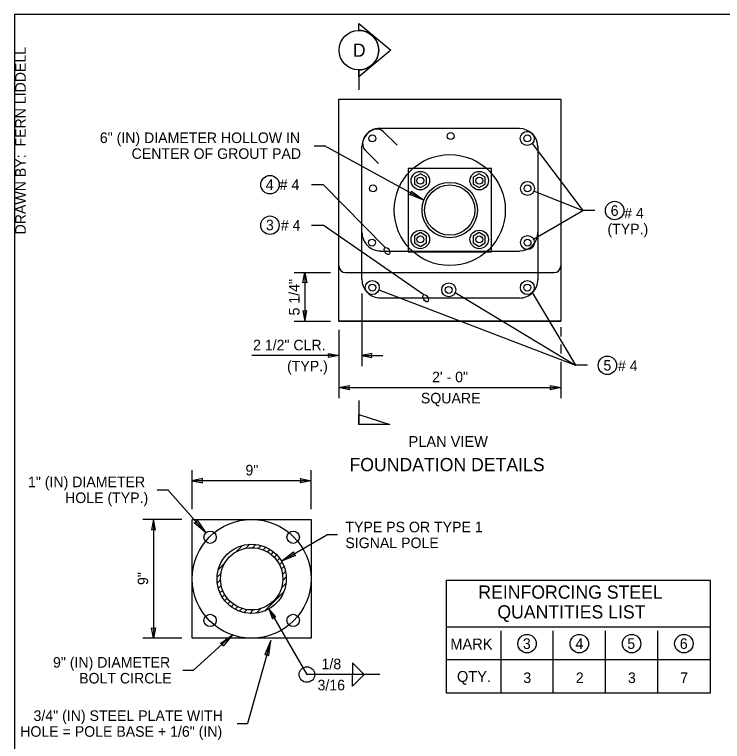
# Model space of a CAD drawing. Extents: x 99862 to 103680, y 99470 to 105076.
# Drawn here: x 99862 to 100935, y 103974 to 105076 of the extents above; entities that cross this region are included whole.
import ezdxf

# ---------------------------------------------------------------- set-up
doc = ezdxf.new("R2010")
doc.units = 0
for name, color, linetype in [('Level 1', 7, 'Continuous'), ('Level 10', 7, 'Continuous'), ('Level 13', 7, 'Continuous'), ('Level 15', 7, 'Continuous'), ('Level 20', 7, 'Continuous'), ('Level 24', 7, 'Continuous'), ('Level 25', 7, 'Continuous'), ('Level 26', 7, 'Continuous'), ('Level 4', 7, 'Continuous'), ('Level 40', 7, 'Continuous'), ('Level 5', 7, 'Continuous'), ('Level 62', 7, 'Continuous'), ('Level 8', 7, 'Continuous'), ('Level 9', 7, 'Continuous')]:
    doc.layers.add(name, color=color, linetype=linetype)

msp = doc.modelspace()

# ---------------------------------------------------------------- linework, layer by layer
at = {"layer": 'Level 1'}
msp.add_line((100363.4, 104684.6), (100679.6, 104684.6), dxfattribs=at)
for points in [[(100353.4, 104947.3), (100689.6, 104947.3), (100689.6, 104774.6)], [(100353.4, 104694.6), (100353.4, 104947.3)], [(100689.6, 104774.6), (100689.6, 104694.6)], [(100689.6, 104694.6), (100689.6, 104611.1), (100353.4, 104611.1), (100353.4, 104694.6)]]:
    msp.add_lwpolyline(points, dxfattribs=at)
for centre, start, end in [((100363.4, 104694.6), 180, 270), ((100679.6, 104694.6), 270, 0)]:
    msp.add_arc(centre, 10, start, end, dxfattribs=at)
at = {"layer": 'Level 10'}
for centre in [(100404, 104887.8), (100523, 104891.3), (100638.9, 104887.8), (100405.2, 104812), (100639.3, 104812), (100403.8, 104730), (100639.3, 104730), (100404.1, 104661.8), (100519.9, 104658.3), (100639, 104661.8)]:
    msp.add_circle(centre, 5.25, dxfattribs=at)
at = {"layer": 'Level 13'}
for p, q in [((100476.9, 104834.3), (100467.8, 104829.1)), ((100467.8, 104829.1), (100467.8, 104818.6)), ((100486, 104829.1), (100476.9, 104834.3)), ((100486, 104818.6), (100486, 104829.1)), ((100566.1, 104834.3), (100557, 104829.1)), ((100557, 104829.1), (100557, 104818.6)), ((100575.2, 104829.1), (100566.1, 104834.3)), ((100575.2, 104818.6), (100575.2, 104829.1)), ((100467.8, 104818.6), (100476.9, 104813.3)), ((100476.9, 104813.3), (100486, 104818.6)), ((100557, 104818.6), (100566.1, 104813.3)), ((100566.1, 104813.3), (100575.2, 104818.6)), ((100476.9, 104745.2), (100467.8, 104739.9)), ((100467.8, 104739.9), (100467.8, 104729.4)), ((100486, 104739.9), (100476.9, 104745.2)), ((100486, 104729.4), (100486, 104739.9)), ((100566.1, 104745.2), (100557, 104739.9)), ((100557, 104739.9), (100557, 104729.4)), ((100575.2, 104739.9), (100566.1, 104745.2)), ((100575.2, 104729.4), (100575.2, 104739.9)), ((100467.8, 104729.4), (100476.9, 104724.1)), ((100476.9, 104724.1), (100486, 104729.4)), ((100557, 104729.4), (100566.1, 104724.1)), ((100566.1, 104724.1), (100575.2, 104729.4))]:
    msp.add_line(p, q, dxfattribs=at)
msp.add_lwpolyline([(100584.6, 104842.3), (100458.5, 104842.3), (100458.5, 104716.2), (100584.6, 104716.2)], close=True, dxfattribs=at)
for centre in [(100476.9, 104823.8), (100566.1, 104823.8), (100476.9, 104734.7), (100566.1, 104734.7)]:
    msp.add_circle(centre, 14, dxfattribs=at)
at = {"layer": 'Level 15'}
for p, q in [((100646.4, 104880.3), (100723.3, 104778.5)), ((100315.8, 104876.8), (100331.8, 104876.8)), ((100482, 104794.2), (100331.8, 104876.8)), ((100311.8, 104817.8), (100329.7, 104817.8)), ((100423.4, 104722.4), (100329.7, 104817.8)), ((100649.4, 104807.9), (100723.3, 104778.5)), ((100648.5, 104735.3), (100723.3, 104778.5)), ((100741.2, 104778.5), (100723.3, 104778.5)), ((100311.8, 104756.2), (100329.7, 104756.2)), ((100482, 104650.8), (100329.7, 104756.2)), ((100285.8, 104684.6), (100340.8, 104684.6)), ((100301.8, 104684.6), (100301.8, 104611.1)), ((100388, 104652.7), (100388, 104542.7)), ((100414.1, 104658.2), (100712.2, 104544.3)), ((100529.8, 104654.3), (100712.2, 104544.3)), ((100646.5, 104654.2), (100712.2, 104544.3)), ((100285.8, 104611.1), (100340.8, 104611.1)), ((100353.4, 104597.6), (100353.4, 104494.2)), ((100689.6, 104601.6), (100689.6, 104587.7)), ((100689.6, 104575.7), (100689.6, 104561.7)), ((100353.4, 104558.7), (100221.6, 104558.7)), ((100387.8, 104558.7), (100419.8, 104558.7)), ((100689.6, 104549.1), (100689.6, 104494.2)), ((100730.1, 104544.3), (100712.2, 104544.3)), ((100353.4, 104510.2), (100689.6, 104510.2)), ((100131.3, 104326.2), (100131.3, 104385.2)), ((100311.3, 104326.2), (100311.3, 104385.2)), ((100311.3, 104369.2), (100131.3, 104369.2)), ((100078.3, 104355.3), (100094.3, 104355.3)), ((100151.7, 104290.1), (100094.3, 104355.3)), ((100115.5, 104310.5), (100056.5, 104310.5)), ((100072.5, 104310.5), (100072.5, 104130.5)), ((100266.4, 104247.2), (100335.3, 104287)), ((100351.3, 104287), (100335.3, 104287)), ((100247.5, 104175.1), (100305, 104075.5)), ((100115.5, 104130.5), (100056.5, 104130.5)), ((100192.8, 104136.2), (100133.1, 104081.9)), ((100250.4, 104127), (100215.1, 104001.2)), ((100374.2, 104093), (100374.2, 104075.5)), ((100374.2, 104093), (100391.7, 104075.5)), ((100117.1, 104081.9), (100133.1, 104081.9)), ((100415.5, 104075.5), (100305, 104075.5)), ((100374.2, 104058), (100391.7, 104075.5)), ((100374.2, 104058), (100374.2, 104075.5)), ((100199.1, 104001.2), (100215.1, 104001.2))]:
    msp.add_line(p, q, dxfattribs=at)
for points in [[(100482, 104794.2), (100460.5, 104802.6), (100462.9, 104804.7), (100463.4, 104807.8)], [(100301.8, 104684.6), (100304.9, 104668.9), (100301.8, 104669.6), (100298.7, 104668.9)], [(100301.8, 104611.1), (100304.9, 104626.8), (100301.8, 104626.1), (100298.7, 104626.8)], [(100353.4, 104558.7), (100337.7, 104555.6), (100338.4, 104558.7), (100337.7, 104561.7)], [(100387.8, 104558.7), (100403.5, 104555.6), (100402.8, 104558.7), (100403.5, 104561.7)], [(100353.4, 104510.2), (100369.1, 104513.3), (100368.4, 104510.2), (100369.1, 104507.1)], [(100689.6, 104510.2), (100673.9, 104507.1), (100674.6, 104510.2), (100673.9, 104513.3)], [(100131.3, 104369.2), (100147, 104366.1), (100146.3, 104369.2), (100147, 104372.3)], [(100311.3, 104369.2), (100295.5, 104366.1), (100296.3, 104369.2), (100295.5, 104372.3)], [(100072.5, 104310.5), (100069.4, 104294.8), (100072.5, 104295.5), (100075.6, 104294.8)], [(100151.7, 104290.1), (100134.3, 104305.2), (100137.3, 104306.4), (100138.8, 104309.2)], [(100266.4, 104247.2), (100284.7, 104261.2), (100285.3, 104258.1), (100287.7, 104256)], [(100247.5, 104175.1), (100252.7, 104159.9), (100255, 104162.1), (100258, 104163)], [(100072.5, 104130.5), (100069.4, 104146.2), (100072.5, 104145.5), (100075.6, 104146.2)], [(100192.8, 104136.2), (100178.2, 104118.4), (100177, 104121.3), (100174.2, 104122.7)], [(100250.4, 104127), (100241.4, 104105.8), (100244.6, 104106), (100247.2, 104104.2)]]:
    msp.add_lwpolyline(points, close=True, dxfattribs=at)
for centre, radius in [((100638.9, 104887.8), 10.6), ((100639.3, 104812), 10.6), ((100639.3, 104730), 10.6), ((100404.1, 104661.8), 10.6), ((100639, 104661.8), 10.6), ((100519.9, 104658.3), 10.6), ((100221.3, 104220.5), 90), ((100305, 104075.5), 11.8)]:
    msp.add_circle(centre, radius, dxfattribs=at)
for centre, major_axis in [((100426.4, 104717.2), (-3, 5.2)), ((100485, 104645.6), (3, -5.2))]:
    msp.add_ellipse(centre, major_axis=major_axis, ratio=0.57735, dxfattribs=at)
at = {"layer": 'Level 20'}
for p, q in [((100383.8, 105051.5), (100383.8, 105062.1)), ((100383.8, 105062.1), (100432.3, 105021.5)), ((100432.3, 105021.5), (100383.8, 104980.9)), ((100383.8, 104980.9), (100383.8, 104991.5)), ((100383.8, 104991.5), (100383.8, 104961.5)), ((100383.8, 104490.6), (100383.8, 104454.1))]:
    msp.add_line(p, q, dxfattribs=at)
msp.add_lwpolyline([(100383.8, 104469.6), (100430.7, 104454.1), (100383.8, 104454.1)], close=True, dxfattribs=at)
for centre, radius in [((100383.8, 105021.5), 30), ((100249.1, 104817.7), 14), ((100771.3, 104778.5), 14), ((100249, 104756.3), 14), ((100760.3, 104544), 14), ((100638.6, 104122.3), 14), ((100717.8, 104122.3), 14), ((100797, 104122.3), 14), ((100876.2, 104122.3), 14)]:
    msp.add_circle(centre, radius, dxfattribs=at)
msp.add_arc((100383.8, 105021.5), 30, 269.9978, 90.0022, dxfattribs=at)
at = {"layer": 'Level 24'}
for radius in [84.1, 42]:
    msp.add_circle((100521.5, 104779.2), radius, dxfattribs=at)
at = {"layer": 'Level 25'}
for p, q in [((100627, 104902.7), (100412.5, 104902.8)), ((100441.6, 104877.8), (100421.3, 104898)), ((100388.3, 104673.8), (100388.4, 104875.7)), ((100393.3, 104870), (100413.5, 104849.7)), ((100655.1, 104876), (100655.1, 104674.1)), ((100388.4, 104745.3), (100388.4, 104768.1)), ((100655.1, 104767.7), (100655.1, 104745.3)), ((100416.4, 104717.2), (100627, 104717.2)), ((100627.1, 104645.9), (100416.4, 104645.9))]:
    msp.add_line(p, q, dxfattribs=at)
for centre, radius, start, end in [((100416.3, 104875), 28, 110.5251, 180), ((100414.2, 104877.7), 25.2, 93.9571, 163.5803), ((100411.4, 104888.1), 14, 45, 110.5201), ((100626.9, 104874.7), 28, 0, 89.9236), ((100403.2, 104879.9), 14, 159.4698, 225), ((100416.4, 104745.3), 28, 179.971, 270), ((100627, 104745.3), 28, 270, 0), ((100416.3, 104673.9), 27.9, 180.1568, 270.3799), ((100627, 104674.1), 28, 315.0487, 0.0004), ((100626.8, 104674), 28.1, 270.5293, 315.481)]:
    msp.add_arc(centre, radius, start, end, dxfattribs=at)
at = {"layer": 'Level 26'}
msp.add_lwpolyline([(99862, 102999.5), (103151, 102999.5), (103151, 105075.5), (99862, 105075.5)], close=True, dxfattribs=at)
at = {"layer": 'Level 4'}
for centre in [(100476.9, 104823.8), (100566.1, 104823.8), (100476.9, 104734.7), (100566.1, 104734.7)]:
    msp.add_circle(centre, 5.25, dxfattribs=at)
at = {"layer": 'Level 40'}
for p, q in [((100516.3, 104147.8), (100915.8, 104147.8)), ((100599, 104141.8), (100599, 104047.4)), ((100678.2, 104047.4), (100678.2, 104141.8)), ((100757.4, 104047.4), (100757.4, 104141.8)), ((100836.6, 104047.4), (100836.6, 104141.8)), ((100915.8, 104097.8), (100516.3, 104097.8))]:
    msp.add_line(p, q, dxfattribs=at)
msp.add_lwpolyline([(100516.3, 104218.4), (100915.8, 104218.4), (100915.8, 104047.4), (100516.3, 104047.4)], close=True, dxfattribs=at)
at = {"layer": 'Level 5'}
for points in [[(100131.3, 104130.5), (100131.3, 104220.5), (100131.3, 104310.5)], [(100131.3, 104310.5), (100221.3, 104310.5), (100311.3, 104310.5)], [(100311.3, 104310.5), (100311.3, 104220.5), (100311.3, 104130.5)], [(100311.3, 104130.5), (100221.3, 104130.5), (100131.3, 104130.5)]]:
    msp.add_lwpolyline(points, dxfattribs=at)
for centre in [(100158.3, 104283.5), (100284.2, 104283.5), (100158.3, 104157.5), (100284.2, 104157.5)]:
    msp.add_circle(centre, 9.38, dxfattribs=at)
at = {"layer": 'Level 8'}
for p, q in [((100197.3, 104261.1), (100207.2, 104271)), ((100212.5, 104266.8), (100218.6, 104272.9)), ((100222.8, 104267.6), (100227.7, 104272.5)), ((100231.3, 104266.6), (100235.6, 104270.9)), ((100238.6, 104264.4), (100242.6, 104268.4)), ((100245, 104261.3), (100248.8, 104265.1)), ((100250.6, 104257.4), (100254.4, 104261.2)), ((100255.6, 104252.9), (100259.3, 104256.6)), ((100259.8, 104247.6), (100263.6, 104251.4)), ((100170.8, 104234.6), (100180.6, 104244.5)), ((100263.4, 104241.7), (100267.3, 104245.6)), ((100168.9, 104223.2), (100174.9, 104229.2)), ((100266.2, 104235), (100270.3, 104239.1)), ((100267.9, 104227.2), (100272.5, 104231.8)), ((100169.2, 104214), (100174.1, 104218.9)), ((100268.4, 104218.2), (100273.6, 104223.4)), ((100170.8, 104206.1), (100175.2, 104210.5)), ((100266.4, 104206.6), (100273.2, 104213.5)), ((100173.3, 104199.1), (100177.4, 104203.2)), ((100176.6, 104192.9), (100180.5, 104196.8)), ((100241.2, 104172), (100269.8, 104200.6)), ((100180.6, 104187.4), (100184.3, 104191.1)), ((100185.1, 104182.4), (100188.9, 104186.2)), ((100190.3, 104178.1), (100194.1, 104181.9)), ((100196.1, 104174.4), (100200, 104178.3)), ((100202.6, 104171.4), (100206.8, 104175.6)), ((100228.2, 104168.5), (100235.1, 104175.4)), ((100210, 104169.3), (100214.5, 104173.8)), ((100218.3, 104168.1), (100223.6, 104173.4))]:
    msp.add_line(p, q, dxfattribs=at)
for centre, radius in [((100521.5, 104779.2), 38.1), ((100221.3, 104220.5), 52.5), ((100221.3, 104220.5), 47.2)]:
    msp.add_circle(centre, radius, dxfattribs=at)
at = {"layer": 'Level 9'}
for p, q in [((100689.6, 104611.1), (100353.4, 104611.1)), ((100353.4, 104611.1), (100689.6, 104611.1))]:
    msp.add_line(p, q, dxfattribs=at)

# ---------------------------------------------------------------- texts
at = {"layer": 'Level 20'}
for s, height, p in [('D', 20, (100374.6, 105011.5)), ('6" (IN) DIAMETER HOLLOW IN', 16, (99991.2, 104880.8)), ('CENTER OF GROUT PAD', 16, (100039.4, 104856.8)), ('4', 16, (100242.7, 104809.7)), ('    # 4', 16, (100240, 104809.8)), ('6', 16, (100765.3, 104770.5)), ('    # 4', 16, (100762, 104766.6)), ('3', 16, (100242.9, 104748.6)), ('    # 4', 16, (100241.7, 104748.2)), ('(TYP.)', 16, (100760.4, 104742.6)), ('2 1/2" CLR.', 16, (100223.4, 104566.7)), ('(TYP.)', 16, (100274.9, 104534.7)), ('5', 16, (100754.3, 104536)), ('    # 4', 16, (100752.5, 104535.3)), ('2\' - 0"', 16, (100494.7, 104518.3)), ('SQUARE', 16, (100477.7, 104486.3)), ('PLAN VIEW', 16.5, (100459.1, 104420.3)), ('FOUNDATION DETAILS', 20, (100369.5, 104383.6)), ('9"', 16, (100211.9, 104377.2)), ('TYPE PS OR TYPE 1 ', 16, (100363.3, 104291)), ('SIGNAL POLE', 16, (100363.3, 104267)), ('REINFORCING STEEL', 20, (100564.8, 104190.4)), ('QUANTITIES LIST', 20, (100593.6, 104160.4)), ('MARK', 16.5, (100522.4, 104113.4)), ('3', 16, (100632.3, 104114.3)), ('4', 16, (100711.9, 104114.3)), ('5', 16, (100790.5, 104114.3)), ('6', 16, (100870.1, 104114.3)), ('9" (IN) DIAMETER', 16, (99920.3, 104085.9)), ('1/8', 16, (100327.2, 104083.5)), ('BOLT CIRCLE', 16, (99959.9, 104061.9)), ('QTY.', 16.5, (100532.4, 104064.3)), ('3', 16, (100633, 104062.6)), ('2', 16, (100712.5, 104062.6)), ('3', 16, (100791.4, 104062.6)), ('7', 16, (100870.7, 104062.6)), ('3/16', 16, (100321.1, 104051.5)), ('3/4" (IN) STEEL PLATE WITH', 16, (99890.8, 104005.2)), ('HOLE = POLE BASE + 1/6" (IN)', 16, (99870.6, 103981.2))]:
    msp.add_text(s, height=height, dxfattribs=at).set_placement(p)
for s, rotation, p in [('5 1/4"', 90, (100293.8, 104619.6)), ('1" (IN) DIAMETER', 360, (99882.4, 104359.3)), ('HOLE (TYP.)', 360, (99938.6, 104335.3)), ('9"', 90, (100064.5, 104211.1))]:
    msp.add_text(s, height=16, rotation=rotation, dxfattribs=at).set_placement(p)
at = {"layer": 'Level 62'}
msp.add_text('DRAWN BY:  FERN LIDDELL', height=16, rotation=90, dxfattribs=at).set_placement((99879, 104742.3))

doc.saveas('drawing.dxf')
